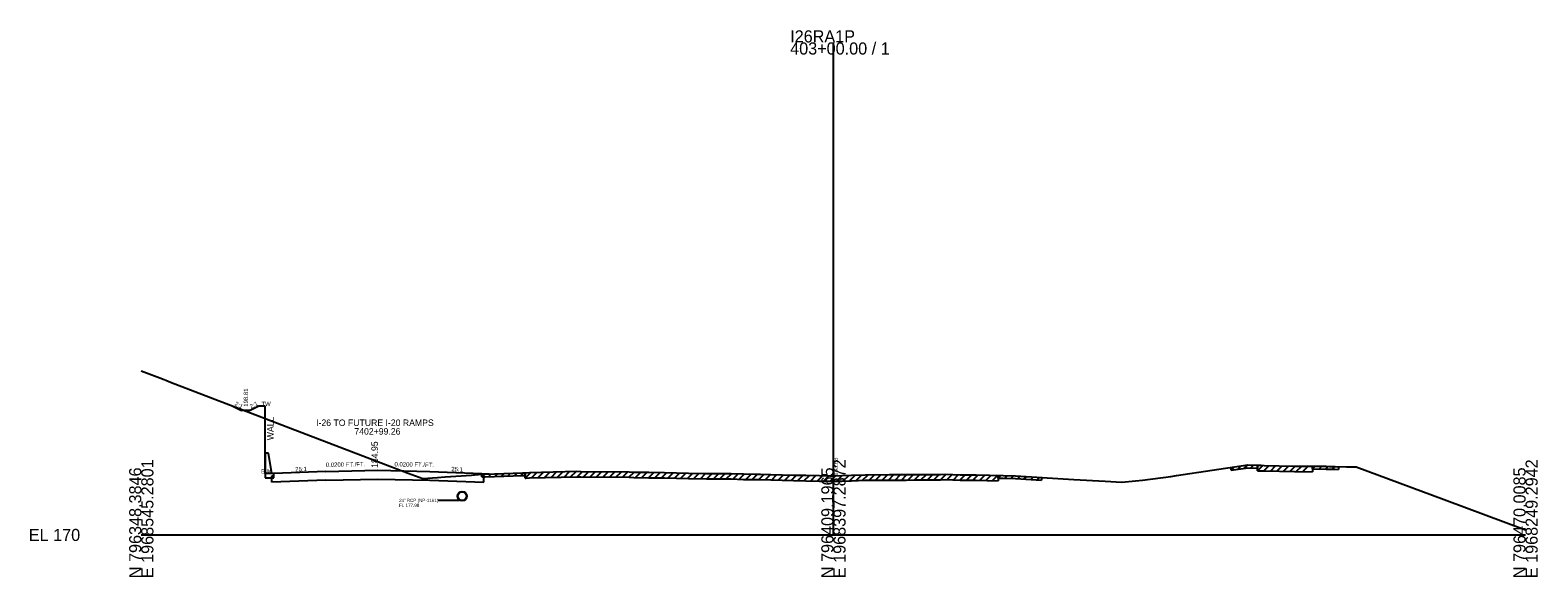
# Model space of a CAD drawing. Extents: x -44 to 4323, y -10 to 9601.
# Drawn here: x -25.7 to 322.8, y 1990.3 to 2116.7 of the extents above; entities that cross this region are included whole.
import ezdxf

# ---------------------------------------------------------------- set-up
doc = ezdxf.new("R2010")
doc.units = 0
for name, color, linetype in [('1', 7, 'Continuous'), ('DateStamp', 7, 'Continuous'), ('NotForConst', 7, 'Continuous'), ('RD_SHT_Bndy', 7, 'Continuous'), ('RD_SHT_Iplotshp', 7, 'Continuous'), ('RD_SHT_TX', 7, 'Continuous'), ('RD_Sketch10', 7, 'Continuous'), ('RD_XS_ExGround', 7, 'Continuous'), ('RD_XS_ExPaveRet', 7, 'Continuous'), ('RD_XS_MatchLine', 7, 'Continuous'), ('RD_XS_Misc_Line', 7, 'Continuous'), ('RD_XS_PaveShd', 7, 'Continuous'), ('RD_XS_Pipe', 7, 'Continuous'), ('RD_XS_TX_Elev_PR', 7, 'Continuous'), ('RD_XS_TX_ShdSlope', 7, 'Continuous'), ('RD_XS_TX_Slope', 7, 'Continuous'), ('seal', 7, 'Continuous'), ('TR SN EXTRUDED PANEL SIGNS - GROUND MOUNTED', 7, 'Continuous')]:
    doc.layers.add(name, color=color, linetype=linetype)

msp = doc.modelspace()

# ---------------------------------------------------------------- linework, layer by layer
at = {"layer": 'DateStamp'}
msp.add_lwpolyline([(0, 2037.97), (4.25, 2036.35), (5.29, 2035.95), (5.71, 2035.78), (6.73, 2035.36), (38.14, 2023.28), (61.67, 2014.27), (65.07, 2013.05), (68.49, 2013.29), (70.23, 2013.42), (72.74, 2013.61), (76.31, 2013.86), (78.73, 2014.04), (79.52, 2014.07), (88.16, 2014.37), (88.9, 2014.4), (89.71, 2014.45), (100.68, 2014.72), (101.59, 2014.71), (112.77, 2014.59), (113.89, 2014.55), (117.32, 2014.49), (120.93, 2014.42), (126.48, 2014.32), (130.68, 2014.23), (135.97, 2014.2), (136.39, 2014.19), (139.2, 2014.11), (141.81, 2014.08), (143.14, 2014.04), (145.53, 2014), (150.78, 2013.84), (153.61, 2013.8), (156.76, 2013.71), (159.12, 2013.67), (160, 2013.68), (160.55, 2013.69), (161.98, 2013.72), (164.18, 2013.8), (167.35, 2013.92), (172.93, 2013.94), (176.84, 2013.95), (178.89, 2013.98), (179.93, 2014), (183.72, 2013.98), (184.74, 2013.96), (185.93, 2014.05), (189.31, 2013.92), (189.81, 2013.92), (191.35, 2013.92), (192.96, 2013.88), (199.22, 2013.77), (202.1, 2013.7), (215.59, 2012.86), (222.81, 2012.43), (226.69, 2012.18), (229.85, 2012.52), (231.46, 2012.69), (237.97, 2013.53), (239.28, 2013.73), (255.77, 2016.18), (258, 2016.11), (258.4, 2016.11), (258.86, 2016.1), (259.59, 2016.07), (266.58, 2015.9), (273.94, 2015.87), (274.64, 2015.86), (275.39, 2015.83), (275.95, 2015.81), (278.62, 2015.77), (280.82, 2015.73), (301.2, 2008.2), (320, 2001.17)], dxfattribs=at)
at = {"layer": 'NotForConst'}
for p, q in [((91.73, 2013.25), (93.01, 2014.53)), ((93.23, 2013.29), (94.51, 2014.57)), ((94.73, 2013.32), (96.01, 2014.6)), ((96.23, 2013.36), (97.51, 2014.64)), ((97.73, 2013.39), (99.01, 2014.67)), ((99.23, 2013.43), (100.51, 2014.71)), ((100.73, 2013.46), (101.97, 2014.7)), ((102.23, 2013.45), (103.47, 2014.69)), ((103.73, 2013.43), (104.97, 2014.67)), ((105.23, 2013.42), (106.47, 2014.66)), ((106.73, 2013.4), (107.97, 2014.64)), ((108.23, 2013.39), (109.47, 2014.63)), ((109.73, 2013.37), (110.97, 2014.61)), ((111.23, 2013.36), (112.47, 2014.59)), ((112.73, 2013.34), (113.94, 2014.55)), ((114.23, 2013.29), (115.46, 2014.52)), ((251.96, 2014.99), (252.7, 2015.72)), ((253.46, 2015.21), (254.2, 2015.94)), ((254.96, 2015.43), (255.7, 2016.17)), ((256.46, 2015.53), (257.07, 2016.14)), ((258, 2014.86), (259.23, 2016.08)), ((259.5, 2014.82), (260.72, 2016.04)), ((261, 2014.78), (262.22, 2016)), ((262.5, 2014.75), (263.72, 2015.97)), ((264, 2014.71), (265.22, 2015.93)), ((265.5, 2014.67), (266.73, 2015.9)), ((267, 2014.65), (268.25, 2015.89)), ((268.5, 2014.64), (269.75, 2015.88)), ((270.76, 2015.26), (271.38, 2015.88)), ((272.26, 2015.25), (272.88, 2015.87)), ((273.76, 2015.24), (274.38, 2015.86)), ((275.26, 2015.21), (275.86, 2015.81)), ((78.73, 2013.41), (79.38, 2014.06)), ((80.23, 2013.47), (80.88, 2014.11)), ((81.73, 2013.52), (82.38, 2014.17)), ((83.23, 2013.57), (83.88, 2014.22)), ((84.73, 2013.62), (85.38, 2014.27)), ((86.23, 2013.68), (86.88, 2014.32)), ((87.73, 2013.73), (88.38, 2014.38)), ((88.73, 2013.14), (90.05, 2014.46)), ((90.23, 2013.21), (91.51, 2014.49)), ((115.73, 2013.27), (116.96, 2014.49)), ((117.23, 2013.24), (118.46, 2014.47)), ((118.73, 2013.21), (119.96, 2014.44)), ((120.23, 2013.18), (121.46, 2014.41)), ((121.73, 2013.16), (122.96, 2014.38)), ((123.23, 2013.13), (124.46, 2014.36)), ((124.73, 2013.1), (125.96, 2014.33)), ((126.24, 2013.08), (127.46, 2014.3)), ((127.74, 2013.04), (128.96, 2014.27)), ((129.24, 2013.01), (130.46, 2014.24)), ((130.74, 2012.98), (131.98, 2014.22)), ((132.24, 2012.97), (133.48, 2014.21)), ((133.74, 2012.96), (134.98, 2014.2)), ((135.24, 2012.95), (136.48, 2014.19)), ((136.74, 2012.93), (137.95, 2014.15)), ((138.24, 2012.89), (139.45, 2014.11)), ((139.74, 2012.85), (140.97, 2014.09)), ((141.24, 2012.83), (142.46, 2014.06)), ((142.74, 2012.8), (143.96, 2014.02)), ((144.24, 2012.77), (145.47, 2014)), ((145.74, 2012.74), (146.95, 2013.96)), ((147.24, 2012.7), (148.45, 2013.91)), ((148.74, 2012.65), (149.95, 2013.86)), ((150.24, 2012.6), (151.46, 2013.83)), ((151.74, 2012.57), (152.97, 2013.81)), ((153.24, 2012.56), (154.46, 2013.78)), ((154.74, 2012.52), (155.95, 2013.73)), ((156.24, 2012.47), (157.46, 2013.7)), ((157.74, 2012.44), (158.97, 2013.67)), ((159.24, 2012.42), (160.51, 2013.69)), ((160.74, 2012.44), (162.02, 2013.72)), ((162.24, 2012.48), (163.54, 2013.78)), ((163.74, 2012.54), (165.04, 2013.83)), ((165.24, 2012.59), (166.54, 2013.89)), ((166.74, 2012.64), (168.01, 2013.92)), ((168.24, 2012.67), (169.49, 2013.92)), ((169.74, 2012.67), (170.99, 2013.93)), ((171.24, 2012.68), (172.5, 2013.93)), ((172.74, 2012.69), (174, 2013.94)), ((174.24, 2012.69), (175.5, 2013.95)), ((175.74, 2012.7), (177, 2013.95)), ((177.24, 2012.71), (178.51, 2013.98)), ((178.74, 2012.73), (180.01, 2014)), ((180.24, 2012.75), (181.48, 2013.99)), ((181.74, 2012.74), (182.98, 2013.98)), ((183.24, 2012.73), (184.48, 2013.97)), ((184.74, 2012.71), (186.07, 2014.04)), ((186.24, 2012.78), (187.45, 2013.99)), ((187.74, 2012.73), (188.95, 2013.94)), ((189.24, 2012.68), (190.49, 2013.92)), ((190.74, 2012.67), (191.98, 2013.9)), ((192.24, 2012.65), (193.47, 2013.87)), ((193.74, 2012.62), (194.97, 2013.85)), ((195.24, 2012.59), (196.47, 2013.82)), ((196.74, 2012.56), (197.97, 2013.79)), ((198.1, 2013.16), (198.71, 2013.78)), ((199.6, 2013.13), (200.21, 2013.74)), ((201.1, 2013.1), (201.71, 2013.71)), ((202.6, 2013.04), (203.19, 2013.63)), ((204.1, 2012.95), (204.69, 2013.54)), ((205.6, 2012.86), (206.19, 2013.44)), ((207.1, 2012.76), (207.69, 2013.35))]:
    msp.add_line(p, q, dxfattribs=at)
at = {"layer": 'RD_SHT_Bndy'}
for p, q in [((160, 2000), (160, 2113.9)), ((0, 2000), (160, 2000)), ((160, 2000), (320, 2000))]:
    msp.add_line(p, q, dxfattribs=at)
at = {"layer": 'RD_SHT_Iplotshp'}
for p, q in [((251.96, 2014.99), (251.96, 2015.61)), ((251.96, 2014.99), (255.77, 2015.55)), ((255.77, 2015.55), (258, 2015.48)), ((258, 2014.86), (258, 2016.11)), ((258, 2016.11), (258, 2015.48)), ((258, 2014.86), (258.4, 2014.86)), ((258.4, 2014.86), (258.86, 2014.85)), ((258.86, 2014.85), (259.59, 2014.82)), ((259.59, 2014.82), (266.58, 2014.65)), ((266.58, 2014.65), (270.76, 2014.63)), ((270.76, 2015.88), (270.76, 2014.63)), ((270.76, 2015.26), (270.76, 2015.88)), ((270.76, 2015.26), (273.94, 2015.24)), ((273.94, 2015.24), (274.64, 2015.24)), ((274.64, 2015.24), (275.39, 2015.21)), ((275.39, 2015.21), (275.95, 2015.18)), ((275.95, 2015.18), (276.79, 2015.17)), ((276.79, 2015.79), (276.79, 2015.17)), ((78.73, 2013.41), (78.73, 2014.04)), ((78.73, 2013.41), (79.52, 2013.44)), ((79.52, 2013.44), (88.16, 2013.74)), ((88.16, 2013.74), (88.73, 2013.77)), ((88.73, 2013.14), (88.73, 2014.39)), ((88.73, 2014.39), (88.73, 2013.77)), ((88.73, 2013.14), (88.9, 2013.15)), ((88.9, 2013.15), (89.71, 2013.2)), ((89.71, 2013.2), (100.68, 2013.47)), ((100.68, 2013.47), (101.59, 2013.46)), ((101.59, 2013.46), (112.77, 2013.34)), ((112.77, 2013.34), (113.89, 2013.3)), ((113.89, 2013.3), (117.32, 2013.24)), ((117.32, 2013.24), (120.93, 2013.17)), ((120.93, 2013.17), (126.48, 2013.07)), ((126.48, 2013.07), (130.68, 2012.98)), ((130.68, 2012.98), (135.97, 2012.95)), ((135.97, 2012.95), (136.39, 2012.94)), ((136.39, 2012.94), (139.2, 2012.86)), ((139.2, 2012.86), (141.81, 2012.83)), ((141.81, 2012.83), (143.14, 2012.79)), ((143.14, 2012.79), (145.53, 2012.75)), ((145.53, 2012.75), (150.78, 2012.59)), ((150.78, 2012.59), (153.61, 2012.55)), ((153.61, 2012.55), (156.76, 2012.46)), ((156.76, 2012.46), (159.12, 2012.42)), ((159.12, 2012.42), (160, 2012.43)), ((160, 2012.43), (160.55, 2012.44)), ((160.55, 2012.44), (161.98, 2012.47)), ((161.98, 2012.47), (164.18, 2012.55)), ((164.18, 2012.55), (167.35, 2012.67)), ((167.35, 2012.67), (172.93, 2012.69)), ((172.93, 2012.69), (176.84, 2012.7)), ((176.84, 2012.7), (178.89, 2012.73)), ((178.89, 2012.73), (179.93, 2012.75)), ((179.93, 2012.75), (183.72, 2012.73)), ((183.72, 2012.73), (184.74, 2012.71)), ((184.74, 2012.71), (185.93, 2012.8)), ((185.93, 2012.8), (189.31, 2012.67)), ((189.31, 2012.67), (189.81, 2012.67)), ((189.81, 2012.67), (191.35, 2012.67)), ((191.35, 2012.67), (192.96, 2012.63)), ((192.96, 2012.63), (198.1, 2012.54)), ((198.1, 2013.79), (198.1, 2012.54)), ((198.1, 2013.16), (198.1, 2013.79)), ((198.1, 2013.16), (199.22, 2013.14)), ((199.22, 2013.14), (202.1, 2013.07)), ((202.1, 2013.07), (208.1, 2012.7)), ((208.1, 2013.32), (208.1, 2012.7))]:
    msp.add_line(p, q, dxfattribs=at)
at = {"layer": 'RD_XS_ExPaveRet'}
for p, q in [((28.67, 2014.23), (28.67, 2029.81)), ((30.67, 2014.23), (28.67, 2014.23))]:
    msp.add_line(p, q, dxfattribs=at)
at = {"layer": 'RD_XS_Misc_Line'}
for p, q in [((30.17, 2013.65), (30.67, 2013.67)), ((30.17, 2012.17), (30.17, 2013.65)), ((42.68, 2012.67), (30.17, 2012.17)), ((30.67, 2013.67), (30.67, 2014.23)), ((42.68, 2012.67), (54.69, 2012.91)), ((54.69, 2012.91), (66.69, 2012.67)), ((66.69, 2012.67), (79.2, 2012.17)), ((78.7, 2013.67), (78.7, 2014.23)), ((79.2, 2013.65), (78.7, 2013.67)), ((79.2, 2012.17), (79.2, 2013.65))]:
    msp.add_line(p, q, dxfattribs=at)
at = {"layer": 'RD_XS_PaveShd'}
for p, q in [((21.17, 2029.81), (23.17, 2028.81)), ((25.17, 2028.81), (23.17, 2028.81)), ((27.17, 2029.81), (25.17, 2028.81)), ((28.67, 2029.81), (27.17, 2029.81)), ((78.7, 2014.23), (80.39, 2014.1))]:
    msp.add_line(p, q, dxfattribs=at)
at = {"layer": 'RD_XS_Pipe'}
msp.add_line((73.52, 2007.98), (68.52, 2007.98), dxfattribs=at)
for radius in [1.1, 1]:
    msp.add_circle((74.19, 2008.98), radius, dxfattribs=at)
at = {"layer": 'RD_XS_TX_Elev_PR'}
for p, q in [((42.68, 2014.71), (30.67, 2014.23)), ((66.69, 2014.71), (78.7, 2014.23))]:
    msp.add_line(p, q, dxfattribs=at)
at = {"layer": 'RD_XS_TX_ShdSlope'}
for p, q in [((29.42, 2018.89), (28.67, 2018.89)), ((28.67, 2018.89), (28.67, 2013.23)), ((30.17, 2014.23), (29.42, 2018.89)), ((28.67, 2013.23), (30.67, 2013.23)), ((30.67, 2014.23), (30.17, 2014.23)), ((30.67, 2013.23), (30.67, 2014.23))]:
    msp.add_line(p, q, dxfattribs=at)
at = {"layer": 'RD_XS_TX_Slope'}
for p, q in [((42.68, 2014.71), (54.69, 2014.95)), ((54.69, 2014.95), (66.69, 2014.71))]:
    msp.add_line(p, q, dxfattribs=at)

# ---------------------------------------------------------------- texts
at = {"layer": '1'}
for s, p in [('I-26 TO FUTURE I-20 RAMPS', (40.41, 2025.2)), ('7402+99.26', (49.26, 2023.2))]:
    msp.add_text(s, height=1.5, dxfattribs=at).set_placement(p)
at = {"layer": 'RD_SHT_Bndy'}
for s, p in [('I26RA1P', (150, 2113.9)), ('403+00.00 / 1', (150, 2111.1)), ('EL 170', (-26, 1998.6))]:
    msp.add_text(s, height=2.8, dxfattribs=at).set_placement(p)
for s, p in [('N 796348.3846', (0, 1990)), ('E 1968545.2801', (2.8, 1990)), ('N 796409.1965', (160, 1990)), ('E 1968397.2872', (162.8, 1990)), ('N 796470.0085', (320, 1990)), ('E 1968249.2942', (322.8, 1990))]:
    msp.add_text(s, height=2.8, rotation=90, dxfattribs=at).set_placement(p)
at = {"layer": 'RD_SHT_TX'}
msp.add_text('183.68', height=1, rotation=90, dxfattribs=at).set_placement((161, 2013.68))
at = {"layer": 'RD_Sketch10'}
for s, p in [('TW', (27.77, 2029.81)), ('BW', (27.69, 2014.23))]:
    msp.add_text(s, height=1, dxfattribs=at).set_placement(p)
at = {"layer": 'RD_XS_ExGround'}
for rotation, p in [(2.2894, (35.61, 2014.68)), (357.7106, (71.65, 2014.76))]:
    msp.add_text('25:1', height=1, rotation=rotation, dxfattribs=at).set_placement(p)
at = {"layer": 'RD_XS_MatchLine'}
msp.add_text('WALL', height=1.5, rotation=90, dxfattribs=at).set_placement((30.58, 2021.9))
at = {"layer": 'RD_XS_Pipe'}
for s, p in [('24" RCP (NP-1161)', (59.59, 2007.61)), ('FL 177.98', (59.59, 2006.48))]:
    msp.add_text(s, height=0.75, dxfattribs=at).set_placement(p)
at = {"layer": 'seal'}
msp.add_text(' 184.95', height=1.5, rotation=90, dxfattribs=at).set_placement((54.69, 2014.95))
at = {"layer": 'TR SN EXTRUDED PANEL SIGNS - GROUND MOUNTED'}
for s, rotation, p in [('198.81', 90, (24.67, 2029.65)), ('2:1', 333.4349, (21.48, 2030.02)), ('2:1', 26.5651, (25.37, 2029.19)), ('0.0200 FT./FT.', 1.1507, (42.66, 2015.71)), ('0.0200 FT./FT.', 358.8616, (58.52, 2015.87))]:
    msp.add_text(s, height=1, rotation=rotation, dxfattribs=at).set_placement(p)

doc.saveas('drawing.dxf')
